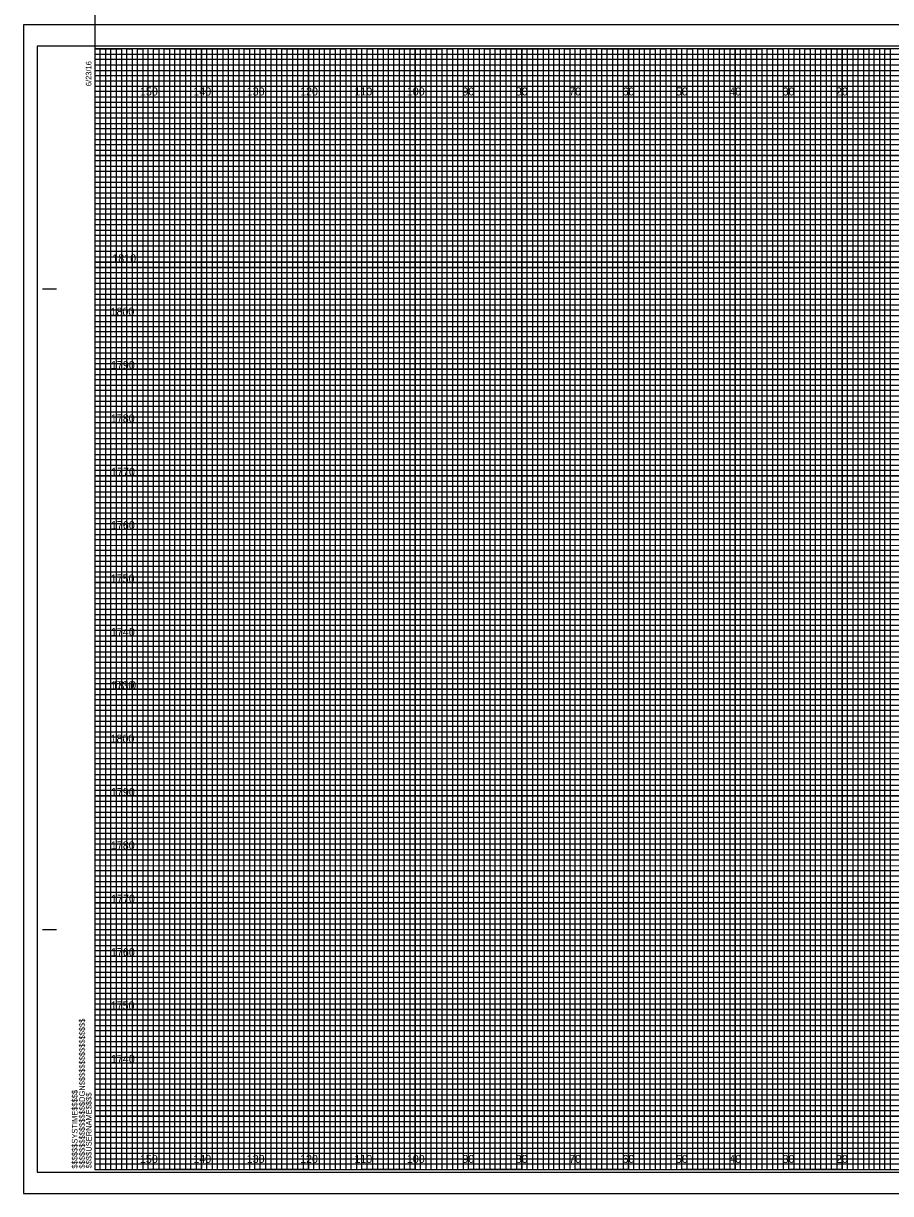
# Model space of a CAD drawing. Extents: x 791 to 1128, y -18 to 860.
# Drawn here: x 791.1 to 953.6, y 201.3 to 420.5 of the extents above; entities that cross this region are included whole.
import ezdxf

# ---------------------------------------------------------------- set-up
doc = ezdxf.new("R2010")
doc.units = 0
for name, color, linetype in [('Prop XS DDE', 7, 'Continuous'), ('Prop XS Earthwork Shape', 7, 'Continuous'), ('Prop XS Subgrade Earthwork', 7, 'Continuous'), ('Raster_Level_0', 7, 'Continuous'), ('Scratch_Level_1', 7, 'Continuous'), ('Scratch_Level_3', 7, 'Continuous'), ('Sheet Cross Section CELL', 7, 'Continuous'), ('Sheet Cross Section Grid Minor 2 CELL', 7, 'Continuous'), ('Sheet Cutting Line CELL', 7, 'Continuous'), ('Sheet DOT Grid CELL', 7, 'Continuous'), ('Sheet Plot Border Inside CELL', 7, 'Continuous'), ('Sheet Plot Border Outside CELL', 7, 'Continuous')]:
    doc.layers.add(name, color=color, linetype=linetype)

msp = doc.modelspace()

# ---------------------------------------------------------------- linework, layer by layer
at = {"layer": 'Prop XS DDE'}
for p, q in [((804.53, 414.75), (1064.53, 414.75)), ((1064.53, 413.73), (804.53, 413.73)), ((804.53, 413.73), (804.53, 412.75)), ((804.53, 412.75), (1064.53, 412.75)), ((1064.53, 411.64), (804.53, 411.64)), ((804.53, 411.64), (804.53, 409.75)), ((804.53, 409.75), (1124.53, 409.75))]:
    msp.add_line(p, q, dxfattribs=at)
for points in [[(804.53, 408.75), (1074.53, 408.75), (1124.53, 408.75), (1124.53, 407.75), (804.53, 407.75)], [(804.53, 406.75), (1124.53, 406.75), (1124.53, 404.75), (804.53, 404.75)], [(804.53, 403.75), (1124.53, 403.75), (1124.53, 402.75), (804.53, 402.73)], [(804.53, 401.75), (1124.53, 401.75), (1124.53, 399.75), (804.53, 399.75)], [(804.53, 398.75), (1124.53, 398.75), (1124.53, 397.75), (804.53, 397.75)], [(804.53, 396.75), (1124.53, 396.75), (1124.53, 394.75), (804.53, 394.75)], [(804.53, 393.75), (1124.53, 393.75), (1124.53, 392.75), (804.53, 392.75)], [(804.53, 391.75), (1124.53, 391.75), (1124.53, 389.75), (804.53, 389.75)], [(804.53, 388.75), (1124.53, 388.75), (1124.53, 387.75), (804.53, 387.75)], [(804.53, 386.75), (1124.53, 386.75), (1124.53, 384.75), (804.53, 384.75)], [(804.53, 383.75), (1124.53, 383.75), (1124.53, 382.75), (804.53, 382.75)], [(804.53, 381.75), (1124.53, 381.75), (1124.53, 379.7), (1124.53, 378.75), (1124.53, 377.75), (804.53, 377.75)], [(804.53, 379.75), (1124.53, 379.75), (1124.53, 378.75), (804.53, 378.75)], [(804.53, 376.75), (1124.53, 376.75), (1124.53, 374.75), (804.53, 374.78)], [(804.53, 374.78), (1124.53, 374.75), (1124.53, 373.75), (804.53, 373.75)], [(804.53, 372.75), (1124.53, 372.75), (1124.53, 371.75), (804.53, 371.75)], [(804.53, 369.75), (1124.53, 369.75), (1124.53, 368.75), (804.53, 368.75)], [(804.53, 367.75), (1124.53, 367.75), (1124.53, 366.75), (804.53, 366.75)], [(804.46, 364.64), (1124.53, 364.64), (1124.53, 363.63), (804.46, 363.63)], [(804.53, 362.75), (1124.53, 362.75), (1124.53, 361.75), (804.53, 361.75)], [(804.53, 359.75), (1124.53, 359.75), (1124.53, 358.75), (804.53, 358.75)], [(804.53, 357.75), (1124.53, 357.75), (1124.53, 356.75), (804.53, 356.75)], [(804.53, 354.75), (1124.53, 354.75), (1124.53, 353.75), (804.53, 353.75)], [(804.53, 352.75), (1124.53, 352.75), (1124.53, 351.75), (804.53, 351.75)], [(804.53, 349.75), (1124.53, 349.75), (1124.53, 348.75), (804.53, 348.75)], [(804.53, 347.75), (1124.53, 347.75), (1124.53, 346.75), (804.53, 346.75)], [(804.53, 344.75), (1124.53, 344.75), (1124.52, 343.73), (804.53, 343.75)], [(804.53, 342.75), (1124.53, 342.75), (1124.53, 341.75), (804.53, 341.75)], [(804.53, 339.75), (1124.53, 339.75), (1124.53, 338.75), (804.53, 338.75)], [(804.53, 337.75), (1124.53, 337.75), (1124.53, 336.75), (804.53, 336.75)], [(804.53, 334.75), (1124.53, 334.75), (1124.53, 333.75), (804.53, 333.75)], [(804.53, 332.75), (1124.53, 332.75), (1124.53, 331.75), (804.53, 331.75)], [(804.53, 329.75), (1124.53, 329.75), (1124.53, 328.75), (804.53, 328.75)], [(804.53, 327.75), (1124.53, 327.75), (1124.53, 326.75), (804.53, 326.75)], [(804.53, 324.75), (1124.53, 324.75), (1124.53, 323.75), (804.53, 323.75)], [(804.53, 322.74), (1124.6, 322.66), (1124.53, 321.75), (804.53, 321.75)], [(804.53, 319.75), (1124.53, 319.75), (1124.53, 318.75), (804.53, 318.75)], [(804.53, 317.75), (1124.53, 317.75), (1124.53, 316.75), (804.53, 316.75)], [(804.53, 314.75), (1124.53, 314.75), (1124.53, 313.75), (804.53, 313.75)], [(804.53, 312.75), (1124.53, 312.75), (1124.53, 311.75), (804.53, 311.75)], [(804.53, 309.75), (1124.53, 309.75), (1124.53, 308.75), (804.53, 308.75)], [(804.53, 307.75), (1124.53, 307.75), (1124.53, 306.75), (804.53, 306.75)], [(804.53, 304.75), (1124.53, 304.75), (1124.53, 303.75), (804.53, 303.75)], [(804.53, 302.75), (1124.53, 302.75), (1124.53, 301.75), (804.53, 301.75)], [(804.53, 299.75), (1124.53, 299.75), (1124.53, 298.75), (804.53, 298.75)], [(804.53, 297.75), (1124.53, 297.75), (1124.53, 296.75), (804.53, 296.75)], [(804.53, 294.75), (1124.53, 294.75), (1124.53, 293.75), (804.53, 293.75)], [(804.53, 292.75), (1124.53, 292.75), (1124.53, 291.75), (804.53, 291.75)], [(804.53, 289.75), (1124.53, 289.75), (1124.53, 288.75), (804.53, 288.75)], [(804.53, 287.75), (1124.53, 287.75), (1124.53, 286.75), (804.53, 286.75)], [(804.53, 284.75), (1124.53, 284.75), (1124.52, 283.73), (804.53, 283.75)], [(804.53, 282.75), (1124.53, 282.75), (1124.53, 281.75), (804.53, 281.75)], [(804.53, 279.75), (1124.53, 279.75), (1124.53, 278.75), (804.53, 278.75)], [(804.53, 277.75), (1124.53, 277.75), (1124.53, 276.75), (804.53, 276.75)], [(804.53, 274.75), (1124.53, 274.75), (1124.53, 273.75), (804.53, 273.75)], [(804.53, 272.75), (1124.53, 272.75), (1124.53, 271.75), (804.53, 271.75)], [(804.53, 269.75), (1124.53, 269.75), (1124.53, 268.75), (804.53, 268.75)], [(804.53, 267.75), (1124.53, 267.75), (1124.53, 266.75), (804.53, 266.75)], [(804.53, 264.75), (1124.53, 264.75), (1124.53, 263.75), (804.53, 263.75)], [(804.53, 262.74), (1124.6, 262.66), (1124.53, 261.75), (804.53, 261.75)], [(804.53, 259.75), (1124.53, 259.75), (1124.53, 258.75), (804.53, 258.75)], [(804.53, 257.75), (1124.53, 257.75), (1124.53, 256.75), (804.53, 256.75)], [(804.53, 254.75), (1124.53, 254.75), (1124.53, 253.75), (804.53, 253.75)], [(804.53, 252.75), (1124.53, 252.75), (1124.53, 251.75), (804.53, 251.75)], [(804.53, 249.75), (1124.53, 249.75), (1124.53, 248.75), (804.53, 248.75)], [(804.53, 247.75), (1124.53, 247.75), (1124.53, 246.75), (804.53, 246.75)], [(804.53, 244.75), (1124.53, 244.75), (1124.53, 243.75), (804.53, 243.75)], [(804.53, 242.75), (1124.53, 242.75), (1124.53, 241.75), (804.53, 241.75)], [(804.53, 239.75), (1124.53, 239.75), (1124.53, 238.75), (804.53, 238.75)], [(804.53, 237.75), (1124.53, 237.75), (1124.53, 236.75), (804.53, 236.75)], [(804.53, 234.75), (1124.53, 234.75), (1124.53, 233.75), (804.53, 233.75)], [(804.53, 232.75), (1124.53, 232.75), (1124.53, 231.75), (804.53, 231.75)], [(804.53, 229.75), (1124.53, 229.75), (1124.53, 228.75), (804.53, 228.75)], [(804.53, 227.75), (1124.53, 227.75), (1124.53, 226.75), (804.53, 226.75)], [(804.53, 224.75), (1124.53, 224.75), (1124.53, 223.75), (804.53, 223.75)], [(804.53, 222.75), (1124.53, 222.75), (1124.53, 221.75), (804.53, 221.75)], [(804.53, 219.75), (1124.53, 219.75), (1124.53, 218.75), (804.53, 218.75)], [(804.53, 217.75), (1124.53, 217.75), (1124.53, 216.75), (804.53, 216.75)], [(804.53, 214.75), (1124.53, 214.75), (1124.53, 213.75), (804.53, 213.75)], [(804.53, 212.75), (1124.53, 212.75), (1124.53, 211.75), (804.53, 211.75)], [(804.53, 209.75), (1124.53, 209.75), (1124.53, 208.75), (804.53, 208.75)], [(804.53, 207.75), (1124.53, 207.75), (1124.53, 206.75), (804.53, 206.75)]]:
    msp.add_lwpolyline(points, dxfattribs=at)
at = {"layer": 'Prop XS Earthwork Shape'}
for points in [[(804.53, 415.75), (809.53, 415.75), (809.53, 205.75), (819.53, 205.75), (819.53, 415.75), (829.53, 415.75), (829.53, 205.75), (839.53, 205.75), (839.53, 415.75), (849.53, 415.75), (849.53, 205.75), (859.53, 205.75), (859.53, 415.75), (869.53, 415.75), (869.53, 205.75), (879.53, 205.75), (879.53, 415.75), (889.53, 415.75), (889.53, 205.75), (899.53, 205.75), (899.53, 415.75), (909.53, 415.75), (909.53, 205.75), (919.53, 205.75), (919.53, 415.75), (929.53, 415.75), (929.53, 205.75), (939.53, 205.75), (939.53, 415.75), (949.53, 415.75), (949.53, 205.75), (959.53, 205.75)], [(804.53, 410.75), (1079.53, 410.75)], [(804.53, 390.75), (1124.53, 390.75), (1124.53, 400.75), (804.53, 400.75)], [(804.53, 370.75), (1124.53, 370.75), (1124.53, 380.75), (804.53, 380.75)], [(804.53, 350.75), (1124.53, 350.75), (1124.53, 360.75), (804.53, 360.75)], [(804.53, 330.75), (1124.53, 330.75), (1124.53, 340.75), (804.53, 340.75)], [(804.53, 310.75), (1124.53, 310.75), (1124.53, 320.75), (804.53, 320.75)], [(804.53, 290.75), (1124.53, 290.75), (1124.53, 300.75), (804.53, 300.75)], [(804.53, 270.75), (1124.53, 270.75), (1124.53, 280.75), (804.53, 280.75)], [(804.53, 250.75), (1124.53, 250.75), (1124.53, 260.75), (804.53, 260.75)], [(804.53, 230.75), (1124.53, 230.75), (1124.53, 240.75), (804.53, 240.75)], [(804.53, 210.75), (1124.53, 210.75), (1124.53, 220.75), (804.53, 220.75)]]:
    msp.add_lwpolyline(points, dxfattribs=at)
at = {"layer": 'Prop XS Subgrade Earthwork'}
msp.add_line((804.53, 425.25), (804.53, 312.36), dxfattribs=at)
at = {"layer": 'Scratch_Level_1'}
for p, q in [((814.53, 415.75), (804.53, 415.75)), ((814.53, 205.75), (814.53, 415.75)), ((834.53, 415.75), (824.53, 415.75)), ((824.53, 415.75), (824.53, 205.75)), ((834.53, 205.75), (834.53, 415.75)), ((854.53, 415.75), (844.53, 415.75)), ((844.53, 415.75), (844.53, 205.75)), ((854.53, 205.75), (854.53, 415.75)), ((874.53, 415.75), (864.53, 415.75)), ((864.53, 415.75), (864.53, 205.75)), ((874.53, 205.75), (874.53, 415.75)), ((894.53, 415.75), (884.53, 415.75)), ((884.53, 415.75), (884.53, 205.75)), ((894.53, 205.75), (894.53, 415.75)), ((914.53, 415.75), (904.53, 415.75)), ((904.53, 415.75), (904.53, 205.75)), ((914.53, 205.75), (914.53, 415.75)), ((934.53, 415.75), (924.53, 415.75)), ((924.53, 415.75), (924.53, 205.75)), ((934.53, 205.75), (934.53, 415.75)), ((954.53, 415.75), (944.53, 415.75)), ((944.53, 415.75), (944.53, 205.75)), ((824.53, 205.75), (814.53, 205.75)), ((844.53, 205.75), (834.53, 205.75)), ((864.53, 205.75), (854.53, 205.75)), ((884.53, 205.75), (874.53, 205.75)), ((904.53, 205.75), (894.53, 205.75)), ((924.53, 205.75), (914.53, 205.75)), ((944.53, 205.75), (934.53, 205.75))]:
    msp.add_line(p, q, dxfattribs=at)
for points in [[(804.53, 405.75), (1124.53, 405.75), (1124.53, 395.75), (804.53, 395.75)], [(804.53, 385.75), (1124.53, 385.75), (1124.53, 375.75), (804.53, 375.75)], [(804.53, 365.75), (1124.53, 365.75), (1124.53, 355.75), (804.53, 355.75)], [(804.53, 345.75), (1124.53, 345.75), (1124.53, 335.75), (804.53, 335.75)], [(804.53, 325.75), (1124.53, 325.75), (1124.53, 315.75), (804.53, 315.75)], [(804.53, 305.75), (1124.53, 305.75), (1124.53, 295.75), (804.53, 295.75)], [(804.53, 285.75), (1124.53, 285.75), (1124.53, 275.75), (804.53, 275.75)], [(804.53, 265.75), (1124.53, 265.75), (1124.53, 255.75), (804.53, 255.75)], [(804.53, 245.75), (1124.53, 245.75), (1124.53, 235.75), (804.53, 235.75)], [(804.53, 225.75), (1124.53, 225.75), (1124.53, 215.75), (804.53, 215.75)]]:
    msp.add_lwpolyline(points, dxfattribs=at)
at = {"layer": 'Sheet Cross Section CELL'}
for p, q in [((794.73, 370.75), (797.23, 370.75)), ((794.83, 370.75), (797.33, 370.75)), ((794.73, 250.75), (797.23, 250.75)), ((794.83, 250.75), (797.33, 250.75)), ((804.53, 205.75), (804.53, 205.75)), ((804.53, 205.75), (804.53, 205.75)), ((804.53, 205.75), (804.53, 205.75)), ((804.53, 205.75), (804.53, 205.75)), ((804.53, 205.75), (804.53, 205.75)), ((804.53, 205.75), (804.53, 205.75)), ((804.53, 205.75), (804.53, 205.75))]:
    msp.add_line(p, q, dxfattribs=at)
msp.add_lwpolyline([(1124.53, 415.75), (804.53, 415.75), (804.53, 205.75), (1124.53, 205.75)], close=True, dxfattribs=at)
at = {"layer": 'Sheet Cross Section Grid Minor 2 CELL'}
for points in [[(804.53, 205.75), (805.53, 205.75), (805.53, 415.75), (806.53, 415.75), (806.53, 205.75)], [(806.53, 205.75), (807.53, 205.75), (807.53, 415.75), (808.53, 415.75), (808.53, 205.75)], [(809.53, 205.75), (810.53, 205.75), (810.53, 415.75), (811.53, 415.75), (811.53, 205.75)], [(811.53, 205.75), (812.53, 205.75), (812.53, 415.75), (813.53, 415.75), (813.53, 205.75)], [(814.53, 205.75), (815.53, 205.75), (815.53, 415.75), (816.53, 415.75), (816.53, 205.75)], [(816.53, 205.75), (817.53, 205.75), (817.53, 415.75), (818.53, 415.75), (818.53, 205.75)], [(819.53, 205.75), (820.53, 205.75), (820.53, 415.75), (821.53, 415.75), (821.53, 205.75)], [(821.53, 205.75), (822.53, 205.75), (822.53, 415.75), (823.53, 415.75), (823.53, 205.75)], [(824.53, 205.75), (825.53, 205.75), (825.53, 415.75), (826.53, 415.75), (826.53, 205.75)], [(826.53, 205.75), (827.53, 205.75), (827.53, 415.75), (828.53, 415.75), (828.53, 205.75)], [(829.53, 205.75), (830.53, 205.75), (830.53, 415.75), (831.53, 415.75), (831.53, 205.75)], [(831.53, 205.75), (832.53, 205.75), (832.53, 415.75), (833.53, 415.75), (833.53, 205.75)], [(834.53, 205.75), (835.53, 205.75), (835.53, 415.75), (836.53, 415.75), (836.53, 205.75)], [(836.53, 205.75), (837.53, 205.75), (837.53, 415.75), (838.53, 415.75), (838.53, 205.75)], [(839.53, 205.75), (840.53, 205.75), (840.53, 415.75), (841.53, 415.75), (841.53, 205.75)], [(841.53, 205.75), (842.53, 205.75), (842.53, 415.75), (843.53, 415.75), (843.53, 205.75)], [(844.53, 205.75), (845.53, 205.75), (845.53, 415.75), (846.53, 415.75), (846.53, 205.75)], [(846.53, 205.75), (847.53, 205.75), (847.53, 415.75), (848.53, 415.75), (848.53, 205.75)], [(849.53, 205.75), (850.53, 205.75), (850.53, 415.75), (851.53, 415.75), (851.53, 205.75)], [(851.53, 205.75), (852.53, 205.75), (852.53, 415.75), (853.53, 415.75), (853.53, 205.75)], [(854.53, 205.75), (855.53, 205.75), (855.53, 415.75), (856.53, 415.75), (856.53, 205.75)], [(856.53, 205.75), (857.53, 205.75), (857.53, 415.75), (858.53, 415.75), (858.53, 205.75)], [(859.53, 205.75), (860.53, 205.75), (860.53, 415.75), (861.53, 415.75), (861.53, 205.75)], [(861.53, 205.75), (862.53, 205.75), (862.53, 415.75), (863.53, 415.75), (863.53, 205.75)], [(864.53, 205.75), (865.53, 205.75), (865.53, 415.75), (866.53, 415.75), (866.53, 205.75)], [(866.53, 205.75), (867.53, 205.75), (867.53, 415.75), (868.53, 415.75), (868.53, 205.75)], [(869.53, 205.75), (870.53, 205.75), (870.53, 415.75), (871.53, 415.75), (871.53, 205.75)], [(871.53, 205.75), (872.53, 205.75), (872.53, 415.75), (873.53, 415.75), (873.53, 205.75)], [(874.53, 205.75), (875.53, 205.75), (875.53, 415.75), (876.53, 415.75), (876.53, 205.75)], [(876.53, 205.75), (877.53, 205.75), (877.53, 415.75), (878.53, 415.75), (878.53, 205.75)], [(879.53, 205.75), (880.53, 205.75), (880.53, 415.75), (881.53, 415.75), (881.53, 205.75)], [(881.53, 205.75), (882.53, 205.75), (882.53, 415.75), (883.53, 415.75), (883.53, 205.75)], [(884.53, 205.75), (885.53, 205.75), (885.53, 415.75), (886.53, 415.75), (886.53, 205.75)], [(886.53, 205.75), (887.53, 205.75), (887.53, 415.75), (888.53, 415.75), (888.53, 205.75)], [(889.53, 205.75), (890.53, 205.75), (890.53, 415.75), (891.53, 415.75), (891.53, 205.75)], [(891.53, 205.75), (892.53, 205.75), (892.53, 415.75), (893.53, 415.75), (893.53, 205.75)], [(894.53, 205.75), (895.53, 205.75), (895.53, 415.75), (896.53, 415.75), (896.53, 205.75)], [(896.53, 205.75), (897.53, 205.75), (897.53, 415.75), (898.53, 415.75), (898.53, 205.75)], [(899.53, 205.75), (900.53, 205.75), (900.53, 415.75), (901.53, 415.75), (901.53, 205.75)], [(901.53, 205.75), (902.53, 205.75), (902.53, 415.75), (903.53, 415.75), (903.53, 205.75)], [(904.53, 205.75), (905.53, 205.75), (905.53, 415.75), (906.53, 415.75), (906.53, 205.75)], [(906.53, 205.75), (907.53, 205.75), (907.53, 415.75), (908.53, 415.75), (908.53, 205.75)], [(909.53, 205.75), (910.53, 205.75), (910.53, 415.75), (911.53, 415.75), (911.53, 205.75)], [(911.53, 205.75), (912.53, 205.75), (912.53, 415.75), (913.53, 415.75), (913.53, 205.75)], [(914.53, 205.75), (915.53, 205.75), (915.53, 415.75), (916.53, 415.75), (916.53, 205.75)], [(916.53, 205.75), (917.53, 205.75), (917.53, 415.75), (918.53, 415.75), (918.53, 205.75)], [(919.53, 205.75), (920.53, 205.75), (920.53, 415.75), (921.53, 415.75), (921.53, 205.75)], [(921.53, 205.75), (922.53, 205.75), (922.53, 415.75), (923.53, 415.75), (923.53, 205.75)], [(924.53, 205.75), (925.53, 205.75), (925.53, 415.75), (926.53, 415.75), (926.53, 205.75)], [(926.53, 205.75), (927.53, 205.75), (927.53, 415.75), (928.53, 415.75), (928.53, 205.75)], [(929.53, 205.75), (930.53, 205.75), (930.53, 415.75), (931.53, 415.75), (931.53, 205.75)], [(931.53, 205.75), (932.53, 205.75), (932.53, 415.75), (933.53, 415.75), (933.53, 205.75)], [(934.53, 205.75), (935.53, 205.75), (935.53, 415.75), (936.53, 415.75), (936.53, 205.75)], [(936.53, 205.75), (937.53, 205.75), (937.53, 415.75), (938.53, 415.75), (938.53, 205.75)], [(939.53, 205.75), (940.53, 205.75), (940.53, 415.75), (941.53, 415.75), (941.53, 205.75)], [(941.53, 205.75), (942.53, 205.75), (942.53, 415.75), (943.53, 415.75), (943.53, 205.75)], [(944.53, 205.75), (945.53, 205.75), (945.53, 415.75), (946.53, 415.75), (946.53, 205.75)], [(946.53, 205.75), (947.53, 205.75), (947.53, 415.75), (948.53, 415.75), (948.53, 205.75)], [(949.53, 205.75), (950.53, 205.75), (950.53, 415.75), (951.53, 415.75), (951.53, 205.75)], [(951.53, 205.75), (952.53, 205.75), (952.53, 415.75), (953.53, 415.75), (953.53, 205.75)]]:
    msp.add_lwpolyline(points, dxfattribs=at)
at = {"layer": 'Sheet Cutting Line CELL'}
for p, q in [((1127.83, 420.25), (791.13, 420.25)), ((791.13, 420.25), (791.13, 201.25)), ((791.13, 201.25), (1127.83, 201.25))]:
    msp.add_line(p, q, dxfattribs=at)
at = {"layer": 'Sheet DOT Grid CELL'}
for p, q in [((814.53, 205.75), (814.53, 415.75)), ((824.53, 205.75), (824.53, 415.75)), ((834.53, 205.75), (834.53, 415.75)), ((844.53, 205.75), (844.53, 415.75)), ((854.53, 205.75), (854.53, 415.75)), ((864.53, 205.75), (864.53, 415.75)), ((874.53, 205.75), (874.53, 415.75)), ((884.53, 205.75), (884.53, 415.75)), ((894.53, 205.75), (894.53, 415.75)), ((904.53, 205.75), (904.53, 415.75)), ((914.53, 205.75), (914.53, 415.75)), ((924.53, 205.75), (924.53, 415.75)), ((934.53, 205.75), (934.53, 415.75)), ((944.53, 205.75), (944.53, 415.75)), ((804.53, 405.75), (1124.53, 405.75)), ((804.53, 395.75), (1124.53, 395.75)), ((804.53, 385.75), (1124.53, 385.75)), ((804.53, 375.75), (1124.53, 375.75)), ((804.53, 365.75), (1124.53, 365.75)), ((804.53, 355.75), (1124.53, 355.75)), ((804.53, 345.75), (1124.53, 345.75)), ((804.53, 335.75), (1124.53, 335.75)), ((804.53, 325.75), (1124.53, 325.75)), ((804.53, 315.75), (1124.53, 315.75)), ((804.53, 305.75), (1124.53, 305.75)), ((804.53, 295.75), (1124.53, 295.75)), ((804.53, 285.75), (1124.53, 285.75)), ((804.53, 275.75), (1124.53, 275.75)), ((804.53, 265.75), (1124.53, 265.75)), ((804.53, 255.75), (1124.53, 255.75)), ((804.53, 245.75), (1124.53, 245.75)), ((804.53, 235.75), (1124.53, 235.75)), ((804.53, 225.75), (1124.53, 225.75)), ((804.53, 215.75), (1124.53, 215.75))]:
    msp.add_line(p, q, dxfattribs=at)
at = {"layer": 'Sheet Plot Border Inside CELL'}
msp.add_lwpolyline([(793.73, 205.25), (1126.93, 205.25), (1126.93, 416.25), (793.73, 416.25)], close=True, dxfattribs=at)
at = {"layer": 'Sheet Plot Border Outside CELL'}
msp.add_lwpolyline([(791.13, 201.25), (1127.83, 201.25), (1127.83, 420.25), (791.13, 420.25)], close=True, dxfattribs=at)

# ---------------------------------------------------------------- texts
at = {"layer": 'Raster_Level_0'}
for s, p in [('150', (812.98, 407)), ('140', (822.98, 407)), ('130', (832.98, 407)), ('120', (842.98, 407)), ('110', (853.16, 407)), ('100', (862.98, 407)), ('90', (873.39, 407)), ('80', (883.39, 407)), ('70', (893.39, 407)), ('60', (903.39, 407)), ('50', (913.39, 407)), ('40', (923.39, 407)), ('30', (933.39, 407)), ('20', (943.39, 407)), ('150', (812.98, 207)), ('140', (822.98, 207)), ('130', (832.98, 207)), ('120', (842.98, 207)), ('110', (853.16, 207)), ('100', (862.98, 207)), ('90', (873.39, 207)), ('80', (883.39, 207)), ('70', (893.39, 207)), ('60', (903.39, 207)), ('50', (913.39, 207)), ('40', (923.39, 207)), ('30', (933.39, 207)), ('20', (943.39, 207))]:
    msp.add_text(s, height=1.5, dxfattribs=at).set_placement(p)
at = {"layer": 'Scratch_Level_3'}
for s, p in [('1810', (807.79, 375.75)), ('1800', (807.46, 365.75)), ('1790', (807.54, 355.75)), ('1780', (807.52, 345.75)), ('1770', (807.57, 335.75)), ('1760', (807.54, 325.75)), ('1750', (807.49, 315.75)), ('1740', (807.54, 305.75)), ('1730', (807.46, 295.75)), ('1810', (807.79, 295.75)), ('1800', (807.46, 285.75)), ('1790', (807.54, 275.75)), ('1780', (807.52, 265.75)), ('1770', (807.57, 255.75)), ('1760', (807.54, 245.75)), ('1750', (807.49, 235.75)), ('1740', (807.54, 225.75))]:
    msp.add_text(s, height=1.5, dxfattribs=at).set_placement(p)
at = {"layer": 'Sheet Cross Section CELL'}
for s, p in [('6/23/16', (803.88, 408.75)), ('$$$$$$$$$$$$$$$$DGN$$$$$$$$$$$$$$$$', (802.65, 205.93)), ('$$$$$$SYSTIME$$$$$', (801.27, 205.93)), ('$$$$USERNAME$$$$', (803.91, 205.98))]:
    msp.add_text(s, height=1.05, rotation=90, dxfattribs=at).set_placement(p)

doc.saveas('drawing.dxf')
